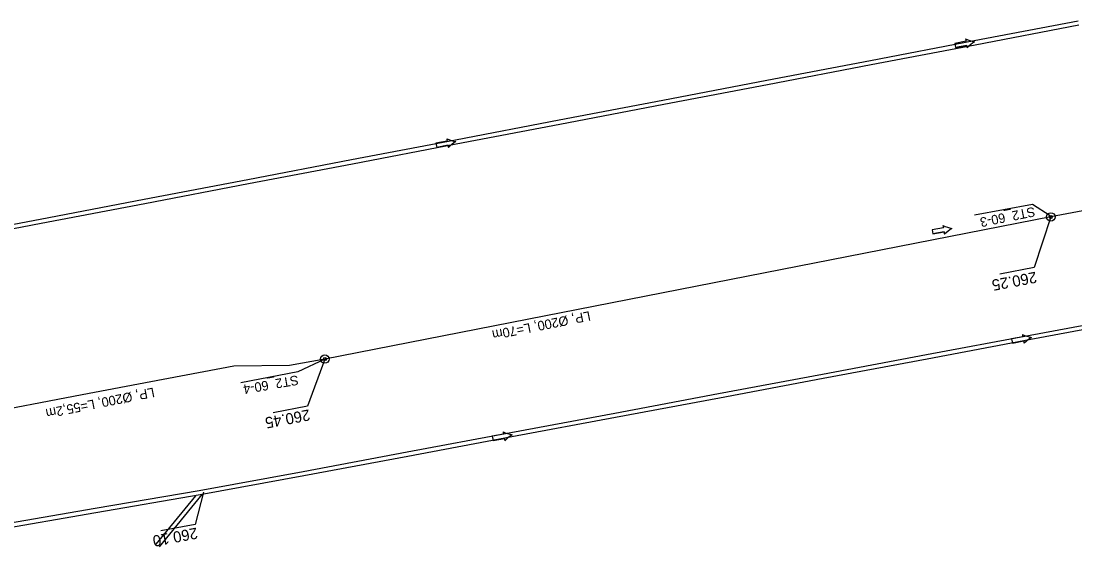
# Model space of a CAD drawing. Extents: x -1 to 65640748, y -22 to 5530284.
# Drawn here: x 6558781.6 to 6558881.4, y 5528911.3 to 5528961.1 of the extents above; entities that cross this region are included whole.
import ezdxf

# ---------------------------------------------------------------- set-up
doc = ezdxf.new("R2010")
doc.units = 0
for name, color, linetype in [('TOR_PS_ODW-drenokolektory', 7, 'Continuous'), ('TOR_PS_ODW-studnie PEHD', 7, 'Continuous'), ('TOR_PS_OPIS_O-opisy rurociagow', 7, 'Continuous'), ('TOR_PS_OPIS_O-opisy studni', 7, 'Continuous'), ('TOR_PS_OPIS_T-INFO', 7, 'Continuous'), ('TOR_PS_T-rowy otwarte umocnione', 7, 'Continuous')]:
    doc.layers.add(name, color=color, linetype=linetype)

msp = doc.modelspace()

# ---------------------------------------------------------------- linework, layer by layer
at = {"layer": 'TOR_PS_ODW-drenokolektory'}
for points in [[(6558938.056, 5528953.581), (6558879.086, 5528942.507)], [(6558879.086, 5528942.507), (6558810.39, 5528929.053)], [(6558810.39, 5528929.053), (6558807.044, 5528928.439), (6558801.771, 5528928.372), (6558793.907, 5528926.881), (6558787.408, 5528925.65), (6558777.206, 5528923.716), (6558771.626, 5528921.937), (6558756.292, 5528919.127)]]:
    msp.add_lwpolyline(points, dxfattribs=at)
at = {"layer": 'TOR_PS_ODW-studnie PEHD'}
for centre, radius in [((6558879.086, 5528942.507), 0.4), ((6558879.086, 5528942.507), 0.145), ((6558810.39, 5528929.053), 0.4), ((6558810.39, 5528929.053), 0.145)]:
    msp.add_circle(centre, radius, dxfattribs=at)
at = {"layer": 'TOR_PS_OPIS_O-opisy rurociagow'}
for p, q in [((6558871.072, 5528959.143), (6558869.999, 5528958.937)), ((6558871.072, 5528959.143), (6558869.999, 5528958.937)), ((6558871.072, 5528959.143), (6558869.999, 5528958.937)), ((6558871.072, 5528959.143), (6558869.999, 5528958.937)), ((6558869.999, 5528958.937), (6558870.075, 5528958.544)), ((6558869.999, 5528958.937), (6558870.075, 5528958.544)), ((6558869.999, 5528958.937), (6558870.075, 5528958.544)), ((6558869.999, 5528958.937), (6558870.075, 5528958.544)), ((6558870.075, 5528958.544), (6558871.148, 5528958.751)), ((6558871.148, 5528958.751), (6558870.075, 5528958.544)), ((6558870.075, 5528958.544), (6558871.148, 5528958.751)), ((6558871.148, 5528958.751), (6558870.075, 5528958.544)), ((6558821.973, 5528949.693), (6558820.9, 5528949.487)), ((6558821.973, 5528949.693), (6558820.9, 5528949.487)), ((6558821.973, 5528949.693), (6558820.9, 5528949.487)), ((6558821.973, 5528949.693), (6558820.9, 5528949.487)), ((6558820.9, 5528949.487), (6558820.976, 5528949.094)), ((6558820.9, 5528949.487), (6558820.976, 5528949.094)), ((6558820.9, 5528949.487), (6558820.976, 5528949.094)), ((6558820.9, 5528949.487), (6558820.976, 5528949.094)), ((6558820.976, 5528949.094), (6558822.049, 5528949.301)), ((6558822.049, 5528949.301), (6558820.976, 5528949.094)), ((6558820.976, 5528949.094), (6558822.049, 5528949.301)), ((6558822.049, 5528949.301), (6558820.976, 5528949.094)), ((6558868.935, 5528941.478), (6558867.859, 5528941.286)), ((6558868.935, 5528941.478), (6558867.859, 5528941.286)), ((6558867.859, 5528941.286), (6558867.929, 5528940.892)), ((6558867.859, 5528941.286), (6558867.929, 5528940.892)), ((6558867.929, 5528940.892), (6558869.005, 5528941.084)), ((6558869.005, 5528941.084), (6558867.929, 5528940.892)), ((6558876.448, 5528931.156), (6558875.374, 5528930.954)), ((6558876.448, 5528931.156), (6558875.374, 5528930.954)), ((6558876.448, 5528931.156), (6558875.374, 5528930.954)), ((6558876.448, 5528931.156), (6558875.374, 5528930.954)), ((6558876.45, 5528931.156), (6558875.376, 5528930.954)), ((6558876.45, 5528931.156), (6558875.376, 5528930.954)), ((6558875.374, 5528930.954), (6558875.448, 5528930.561)), ((6558875.374, 5528930.954), (6558875.448, 5528930.561)), ((6558875.374, 5528930.954), (6558875.448, 5528930.561)), ((6558875.374, 5528930.954), (6558875.448, 5528930.561)), ((6558875.376, 5528930.954), (6558875.449, 5528930.561)), ((6558875.376, 5528930.954), (6558875.449, 5528930.561)), ((6558875.448, 5528930.561), (6558876.522, 5528930.763)), ((6558876.522, 5528930.763), (6558875.448, 5528930.561)), ((6558875.448, 5528930.561), (6558876.522, 5528930.763)), ((6558876.522, 5528930.763), (6558875.448, 5528930.561)), ((6558875.449, 5528930.561), (6558876.523, 5528930.763)), ((6558876.523, 5528930.763), (6558875.449, 5528930.561)), ((6558827.306, 5528921.936), (6558826.232, 5528921.734)), ((6558827.306, 5528921.936), (6558826.232, 5528921.734)), ((6558827.306, 5528921.936), (6558826.232, 5528921.734)), ((6558827.306, 5528921.936), (6558826.232, 5528921.734)), ((6558826.232, 5528921.734), (6558826.306, 5528921.341)), ((6558826.232, 5528921.734), (6558826.306, 5528921.341)), ((6558826.232, 5528921.734), (6558826.306, 5528921.341)), ((6558826.232, 5528921.734), (6558826.306, 5528921.341)), ((6558827.307, 5528921.936), (6558826.233, 5528921.735)), ((6558827.307, 5528921.936), (6558826.233, 5528921.735)), ((6558826.233, 5528921.735), (6558826.307, 5528921.341)), ((6558826.233, 5528921.735), (6558826.307, 5528921.341)), ((6558826.306, 5528921.341), (6558827.38, 5528921.543)), ((6558827.38, 5528921.543), (6558826.306, 5528921.341)), ((6558826.306, 5528921.341), (6558827.38, 5528921.543)), ((6558827.38, 5528921.543), (6558826.306, 5528921.341)), ((6558826.307, 5528921.341), (6558827.381, 5528921.543)), ((6558827.381, 5528921.543), (6558826.307, 5528921.341))]:
    msp.add_line(p, q, dxfattribs=at)
for points in [[(6558871.019, 5528959.362), (6558871.019, 5528959.362)], [(6558871.019, 5528959.362), (6558871.019, 5528959.362)], [(6558871.18, 5528958.528), (6558871.18, 5528958.528)], [(6558871.18, 5528958.528), (6558871.18, 5528958.528)], [(6558821.921, 5528949.912), (6558821.921, 5528949.912)], [(6558821.921, 5528949.912), (6558821.921, 5528949.912)], [(6558822.081, 5528949.078), (6558822.081, 5528949.078)], [(6558822.081, 5528949.078), (6558822.081, 5528949.078)], [(6558868.886, 5528941.697), (6558868.886, 5528941.697)], [(6558869.034, 5528940.861), (6558869.034, 5528940.861)], [(6558876.397, 5528931.375), (6558876.397, 5528931.375)], [(6558876.397, 5528931.375), (6558876.397, 5528931.375)], [(6558876.398, 5528931.375), (6558876.398, 5528931.375)], [(6558876.553, 5528930.54), (6558876.553, 5528930.54)], [(6558876.553, 5528930.54), (6558876.553, 5528930.54)], [(6558876.555, 5528930.54), (6558876.555, 5528930.54)], [(6558827.254, 5528922.155), (6558827.254, 5528922.155)], [(6558827.254, 5528922.155), (6558827.254, 5528922.155)], [(6558827.255, 5528922.155), (6558827.255, 5528922.155)], [(6558827.411, 5528921.32), (6558827.411, 5528921.32)], [(6558827.411, 5528921.32), (6558827.411, 5528921.32)], [(6558827.412, 5528921.32), (6558827.412, 5528921.32)]]:
    msp.add_lwpolyline(points, dxfattribs=at)
for centre, radius, start, end in [((6558872.926, 5528963.895), 4.918, 247.18433, 257.56616), ((6558871.477, 5528959.357), 0.458, 179.2989, 207.76014), ((6558872.926, 5528963.895), 4.918, 247.18433, 257.56616), ((6558871.477, 5528959.357), 0.458, 179.2989, 207.76014), ((6558872.926, 5528963.895), 4.918, 247.18433, 257.56616), ((6558871.477, 5528959.357), 0.458, 179.2989, 207.76014), ((6558872.926, 5528963.895), 4.918, 247.18433, 257.56616), ((6558871.477, 5528959.357), 0.458, 179.2989, 207.76014), ((6558874.633, 5528955.026), 4.918, 124.22222, 134.60405), ((6558874.633, 5528955.026), 4.918, 124.22222, 134.60405), ((6558874.633, 5528955.026), 4.918, 124.22222, 134.60405), ((6558874.633, 5528955.026), 4.918, 124.22222, 134.60405), ((6558871.603, 5528958.703), 0.458, 174.02824, 202.48948), ((6558871.603, 5528958.703), 0.458, 174.02824, 202.48948), ((6558871.603, 5528958.703), 0.458, 174.02824, 202.48948), ((6558871.603, 5528958.703), 0.458, 174.02824, 202.48948), ((6558823.828, 5528954.445), 4.918, 247.17871, 257.56053), ((6558822.378, 5528949.907), 0.458, 179.29327, 207.75451), ((6558823.828, 5528954.445), 4.918, 247.17871, 257.56053), ((6558822.378, 5528949.907), 0.458, 179.29327, 207.75451), ((6558823.828, 5528954.445), 4.918, 247.17871, 257.56053), ((6558822.378, 5528949.907), 0.458, 179.29327, 207.75451), ((6558823.828, 5528954.445), 4.918, 247.17871, 257.56053), ((6558822.378, 5528949.907), 0.458, 179.29327, 207.75451), ((6558822.504, 5528949.253), 0.458, 174.02262, 202.48386), ((6558822.504, 5528949.253), 0.458, 174.02262, 202.48386), ((6558822.504, 5528949.253), 0.458, 174.02262, 202.48386), ((6558822.504, 5528949.253), 0.458, 174.02262, 202.48386), ((6558825.534, 5528945.576), 4.918, 124.21659, 134.59842), ((6558825.534, 5528945.576), 4.918, 124.21659, 134.59842), ((6558825.534, 5528945.576), 4.918, 124.21659, 134.59842), ((6558825.534, 5528945.576), 4.918, 124.21659, 134.59842), ((6558869.343, 5528941.685), 0.458, 178.49555, 206.95679), ((6558869.343, 5528941.685), 0.458, 178.49555, 206.95679), ((6558870.856, 5528946.203), 4.918, 246.38098, 256.76281), ((6558870.856, 5528946.203), 4.918, 246.38098, 256.76281), ((6558869.46, 5528941.03), 0.458, 173.22489, 201.68613), ((6558869.46, 5528941.03), 0.458, 173.22489, 201.68613), ((6558872.438, 5528937.311), 4.918, 123.41887, 133.8007), ((6558872.438, 5528937.311), 4.918, 123.41887, 133.8007), ((6558878.324, 5528935.899), 4.918, 246.92142, 257.30325), ((6558876.854, 5528931.367), 0.458, 179.03598, 207.49722), ((6558878.324, 5528935.899), 4.918, 246.92142, 257.30325), ((6558876.854, 5528931.367), 0.458, 179.03598, 207.49722), ((6558878.324, 5528935.899), 4.918, 246.92142, 257.30325), ((6558876.854, 5528931.367), 0.458, 179.03598, 207.49722), ((6558878.324, 5528935.899), 4.918, 246.92142, 257.30325), ((6558876.854, 5528931.367), 0.458, 179.03598, 207.49722), ((6558878.326, 5528935.899), 4.918, 246.92248, 257.3043), ((6558876.856, 5528931.367), 0.458, 179.03704, 207.49828), ((6558878.326, 5528935.899), 4.918, 246.92248, 257.3043), ((6558876.856, 5528931.367), 0.458, 179.03704, 207.49828), ((6558879.991, 5528927.022), 4.918, 123.95931, 134.34113), ((6558879.991, 5528927.022), 4.918, 123.95931, 134.34113), ((6558879.991, 5528927.022), 4.918, 123.95931, 134.34113), ((6558879.991, 5528927.022), 4.918, 123.95931, 134.34113), ((6558879.992, 5528927.023), 4.918, 123.96036, 134.34219), ((6558879.992, 5528927.023), 4.918, 123.96036, 134.34219), ((6558876.977, 5528930.713), 0.458, 173.76533, 202.22657), ((6558876.977, 5528930.713), 0.458, 173.76533, 202.22657), ((6558876.977, 5528930.713), 0.458, 173.76533, 202.22657), ((6558876.977, 5528930.713), 0.458, 173.76533, 202.22657), ((6558876.978, 5528930.713), 0.458, 173.76639, 202.22763), ((6558876.978, 5528930.713), 0.458, 173.76639, 202.22763), ((6558829.182, 5528926.679), 4.918, 246.91684, 257.29867), ((6558827.712, 5528922.147), 0.458, 179.03141, 207.49265), ((6558829.182, 5528926.679), 4.918, 246.91684, 257.29867), ((6558827.712, 5528922.147), 0.458, 179.03141, 207.49265), ((6558829.182, 5528926.679), 4.918, 246.91684, 257.29867), ((6558827.712, 5528922.147), 0.458, 179.03141, 207.49265), ((6558829.182, 5528926.679), 4.918, 246.91684, 257.29867), ((6558827.712, 5528922.147), 0.458, 179.03141, 207.49265), ((6558829.184, 5528926.679), 4.918, 246.91579, 257.29761), ((6558827.713, 5528922.147), 0.458, 179.03035, 207.49159), ((6558829.184, 5528926.679), 4.918, 246.91579, 257.29761), ((6558827.713, 5528922.147), 0.458, 179.03035, 207.49159), ((6558827.835, 5528921.493), 0.458, 173.76076, 202.222), ((6558827.835, 5528921.493), 0.458, 173.76076, 202.222), ((6558827.835, 5528921.493), 0.458, 173.76076, 202.222), ((6558827.835, 5528921.493), 0.458, 173.76076, 202.222), ((6558827.836, 5528921.493), 0.458, 173.7597, 202.22094), ((6558827.836, 5528921.493), 0.458, 173.7597, 202.22094), ((6558830.848, 5528917.802), 4.918, 123.95473, 134.33656), ((6558830.848, 5528917.802), 4.918, 123.95473, 134.33656), ((6558830.848, 5528917.802), 4.918, 123.95473, 134.33656), ((6558830.848, 5528917.802), 4.918, 123.95473, 134.33656), ((6558830.849, 5528917.802), 4.918, 123.95368, 134.3355), ((6558830.849, 5528917.802), 4.918, 123.95368, 134.3355)]:
    msp.add_arc(centre, radius, start, end, dxfattribs=at)
at = {"layer": 'TOR_PS_OPIS_T-INFO'}
for points in [[(6558879.018, 5528942.597), (6558877.359, 5528943.679), (6558871.862, 5528942.672)], [(6558879.086, 5528942.507), (6558877.503, 5528937.724), (6558874.27, 5528937.1)], [(6558810.39, 5528929.053), (6558807.826, 5528927.824), (6558802.434, 5528926.784)], [(6558810.39, 5528929.053), (6558808.747, 5528924.587), (6558805.513, 5528923.963)], [(6558798.916, 5528916.441), (6558798.113, 5528913.396), (6558794.879, 5528912.772)]]:
    msp.add_lwpolyline(points, dxfattribs=at)
at = {"layer": 'TOR_PS_T-rowy otwarte umocnione'}
for p, q in [((6558794.433, 5528911.512), (6558798.172, 5528916.112)), ((6558794.743, 5528911.26), (6558798.771, 5528916.215))]:
    msp.add_line(p, q, dxfattribs=at)
for points in [[(6558881.673, 5528961.053), (6558871.851, 5528959.174), (6558862.029, 5528957.296), (6558852.207, 5528955.417), (6558842.385, 5528953.538), (6558832.563, 5528951.66), (6558822.741, 5528949.781), (6558812.919, 5528947.903), (6558803.097, 5528946.024), (6558793.275, 5528944.145), (6558783.453, 5528942.267), (6558773.631, 5528940.388)], [(6558881.747, 5528960.66), (6558871.925, 5528958.781), (6558862.103, 5528956.903), (6558852.281, 5528955.024), (6558842.459, 5528953.145), (6558832.637, 5528951.267), (6558822.815, 5528949.388), (6558812.993, 5528947.51), (6558803.171, 5528945.631), (6558793.35, 5528943.752), (6558783.528, 5528941.874), (6558773.706, 5528939.995)], [(6558886.966, 5528933.126), (6558877.138, 5528931.279), (6558867.31, 5528929.436), (6558857.481, 5528927.594), (6558847.652, 5528925.751), (6558837.823, 5528923.909), (6558827.994, 5528922.066), (6558818.166, 5528920.224), (6558808.337, 5528918.381), (6558798.501, 5528916.574), (6558788.643, 5528914.885), (6558778.786, 5528913.192)], [(6558887.041, 5528932.733), (6558877.213, 5528930.886), (6558867.384, 5528929.043), (6558857.555, 5528927.201), (6558847.727, 5528925.358), (6558837.898, 5528923.516), (6558828.069, 5528921.673), (6558818.24, 5528919.831), (6558808.411, 5528917.988), (6558798.576, 5528916.181), (6558788.718, 5528914.492), (6558778.861, 5528912.799)]]:
    msp.add_lwpolyline(points, dxfattribs=at)

# ---------------------------------------------------------------- texts
at = {"layer": 'TOR_PS_OPIS_O-opisy rurociagow'}
for s, p in [('LP, Ø200, L=70m', (6558835.43, 5528933.593)), ('LP, Ø200, L=55,2m', (6558794.171, 5528926.358))]:
    msp.add_text(s, height=0.9, rotation=191.29864, dxfattribs=at).set_placement(p)
at = {"layer": 'TOR_PS_OPIS_O-opisy studni'}
for s, rotation, p in [('ST2_60-3', 191.49789, (6558877.505, 5528943.465)), ('ST2_60-4', 189.92316, (6558807.812, 5528927.519))]:
    msp.add_text(s, height=0.9, rotation=rotation, dxfattribs=at).set_placement(p)
at = {"layer": 'TOR_PS_OPIS_T-INFO'}
for s, p in [('260.25', (6558877.656, 5528937.329)), ('260.45', (6558808.881, 5528924.292)), ('260.10', (6558798.244, 5528913.1))]:
    msp.add_text(s, height=1.05, rotation=190.71587, dxfattribs=at).set_placement(p)

doc.saveas('drawing.dxf')
